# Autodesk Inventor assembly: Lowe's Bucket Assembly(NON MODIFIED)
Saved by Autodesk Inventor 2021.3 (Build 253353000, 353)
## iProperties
Created: 2022-12
Part Number: Lowe's Bucket Assembly(NON MODIFIED)
Document SubType Name: Assembly
Designer: AdminForWorker
Title: Lowe's Bucket Assembly(NON MODIFIED) v1
Author: AdminForWorker
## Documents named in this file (3)
- c:\worker\convert-fusion-r07-cosv3\tmp\job-1\248\output\files\02726f4c-9815-42dc-95dc-176fb5068647\Lowe's Bucket Assembly(NON MODIFIED) v1.iam
- c:\worker\convert-fusion-r07-cosv3\tmp\job-1\248\output\files\02726f4c-9815-42dc-95dc-176fb5068647\Lowe's 5 Gallon Bucket NON ALTERED.ipt
- c:\worker\convert-fusion-r07-cosv3\tmp\job-1\248\output\files\02726f4c-9815-42dc-95dc-176fb5068647\Lowe's Bucket Handle Assembly.iam
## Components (2 placed, 2 different names)
1. Lowe's 5 Gallon Bucket NON ALTERED:1
2. Lowe's Bucket Handle Assembly:1 [sub-assembly]
